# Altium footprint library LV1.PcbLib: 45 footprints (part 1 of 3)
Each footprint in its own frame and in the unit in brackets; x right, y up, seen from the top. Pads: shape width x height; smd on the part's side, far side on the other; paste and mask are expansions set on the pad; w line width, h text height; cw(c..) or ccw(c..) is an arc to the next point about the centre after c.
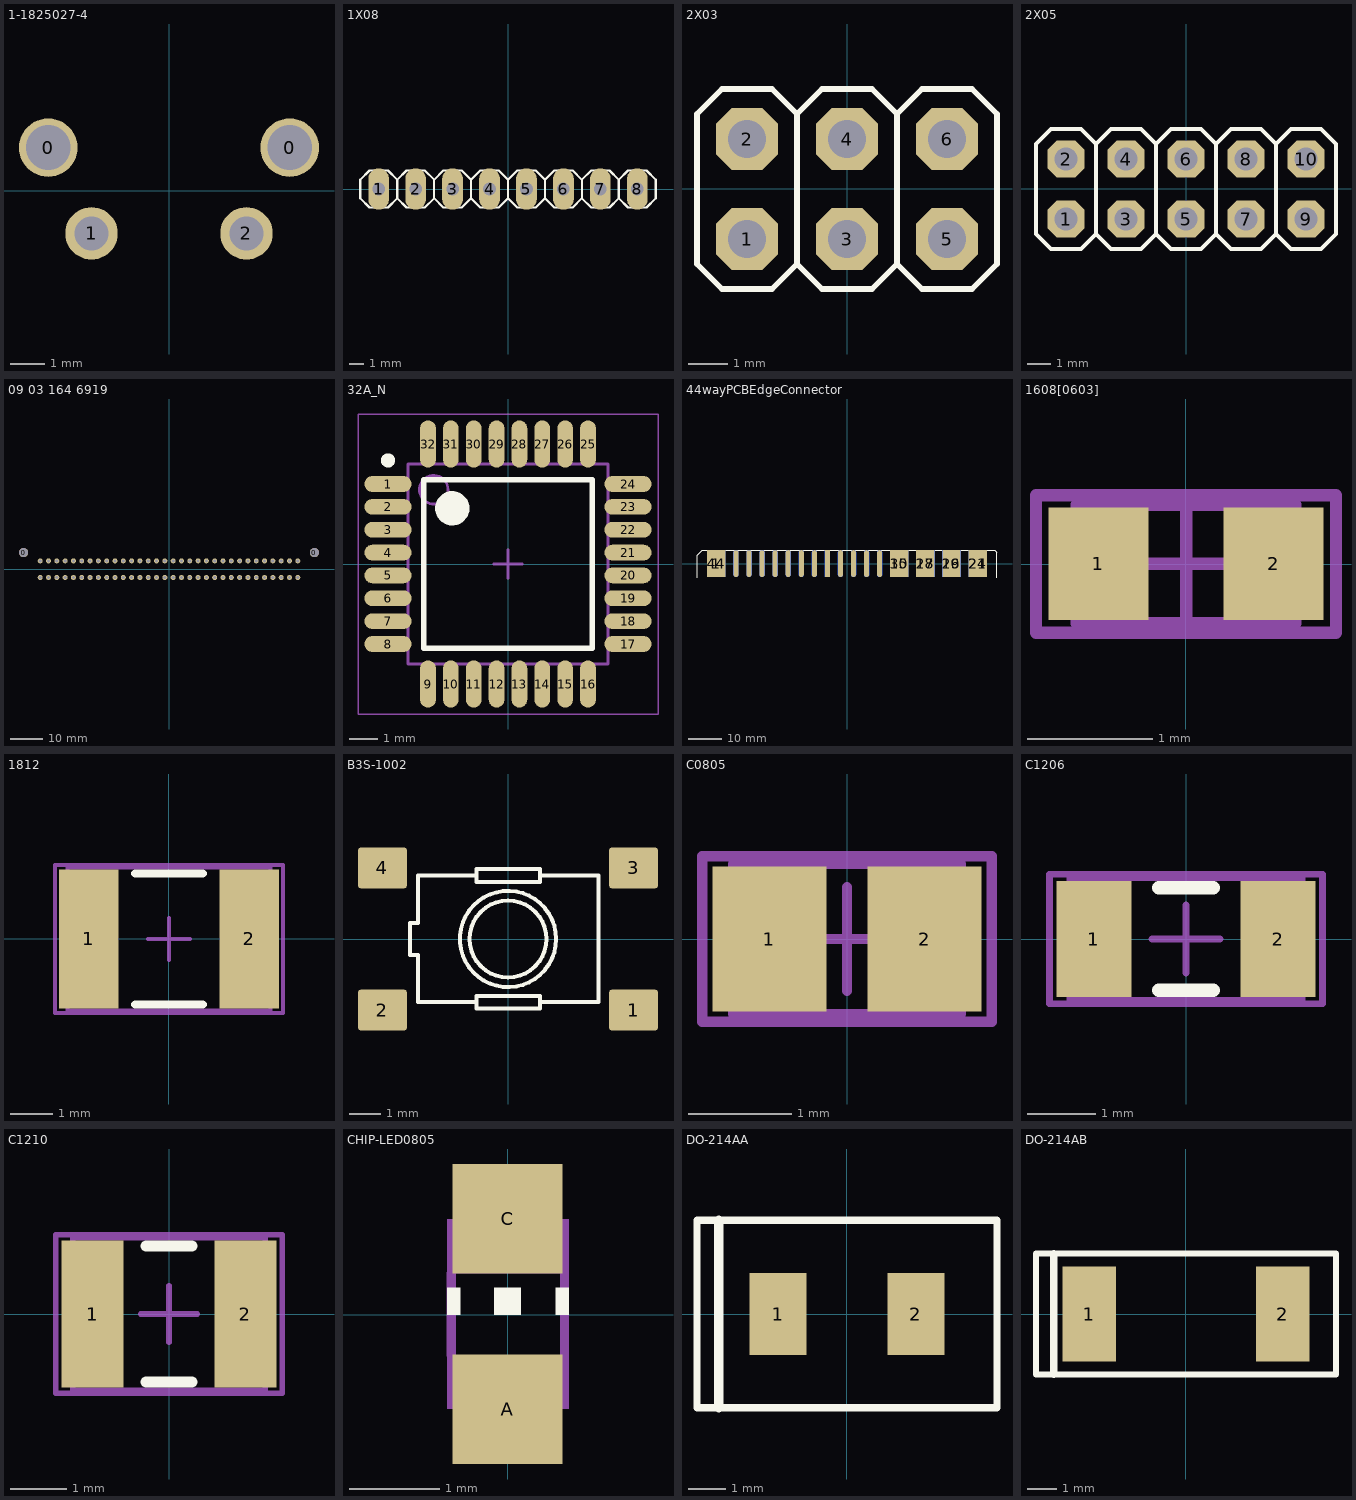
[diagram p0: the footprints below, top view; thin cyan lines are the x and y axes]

## 1-1825027-4 [mm]
pads (4):
  round 1.7 hole 1.3: 0(-3.505,1.245) 0(3.505,1.245)
  round 1.524 hole 0.99: 1(-2.25,-1.245) 2(2.25,-1.245)
3D body "c-1-1825027-4-g1-3d.stp": height 7, standoff -3.52, extent -4.204,-7.366 4.204,2.781

## 1X08 [mil]
height 338.58
pads (8):
  oval 56x112 hole 34: 1(-350,0) 2(-250,0) 3(-150,0) 4(-50,0) 5(50,0) 6(150,0) 7(250,0) 8(350,0)
Top Overlay:
  lines w6: -300,-25 -300,25 ; -300,-25 -325,-50 -375,-50 -400,-25 -400,25 -375,50 -325,50 -300,25 ; -300,-25 -275,-50 -225,-50 -200,-25 ; -300,25 -275,50 -225,50 -200,25 ; -200,-25 -175,-50 -125,-50 -100,-25 ; -200,-25 -200,25 ; -200,25 -175,50 -125,50 -100,25 ; -100,-25 -100,25 ; -100,-25 -75,-50 -25,-50 0,-25 ; -100,25 -75,50 -25,50 0,25 ; 0,-25 0,25 ; 0,-25 25,-50 75,-50 100,-25 ; 0,25 25,50 75,50 100,25 ; 100,-25 125,-50 175,-50 200,-25 ; 100,-25 100,25 ; 100,25 125,50 175,50 200,25 ; 200,-25 200,25 ; 200,-25 225,-50 275,-50 300,-25 ; 200,25 225,50 275,50 300,25 ; 300,-25 300,25 ; 300,-25 325,-50 375,-50 400,-25 400,25 375,50 325,50 300,25
Mechanical 16:
  rectangle: 240,-10 260,10
  rectangle: 140,-10 160,10
  rectangle: 40,-10 60,10
  rectangle: -60,-10 -40,10
  rectangle: -160,-10 -140,10
  rectangle: -260,-10 -240,10
  rectangle: -360,-10 -340,10
  rectangle: 340,-10 360,10

## 2X03 [mil]
height 338.58
pads (6):
  oct 62x62 hole 38: 1(-100,-50) 2(-100,50) 3(0,-50) 4(0,50) 5(100,-50) 6(100,50)
Top Overlay:
  lines w6: -50,-75 -75,-100 -125,-100 -150,-75 -150,75 -125,100 -75,100 -50,75 ; -50,-75 -25,-100 25,-100 50,-75 ; -50,-75 -50,75 ; -50,75 -25,100 25,100 50,75 ; 50,-75 50,75 ; 50,-75 75,-100 125,-100 150,-75 150,75 125,100 75,100 50,75
Mechanical 16:
  rectangle: -110,-60 -90,-40
  rectangle: -110,40 -90,60
  rectangle: -10,40 10,60
  rectangle: -10,-60 10,-40
  rectangle: 90,40 110,60
  rectangle: 90,-60 110,-40

## 2X05 [mil]
height 338.58
pads (10):
  oct 62x62 hole 38: 1(-200,-50) 2(-200,50) 3(-100,-50) 4(-100,50) 5(0,-50) 6(0,50) 7(100,-50) 8(100,50) 9(200,-50) 10(200,50)
Top Overlay:
  lines w6: -150,-75 -150,75 ; -150,-75 -125,-100 -75,-100 -50,-75 ; -150,-75 -175,-100 -225,-100 -250,-75 -250,75 -225,100 -175,100 -150,75 ; -150,75 -125,100 -75,100 -50,75 ; -50,-75 -25,-100 25,-100 50,-75 ; -50,-75 -50,75 ; -50,75 -25,100 25,100 50,75 ; 50,-75 50,75 ; 50,-75 75,-100 125,-100 150,-75 ; 50,-75 50,75 ; 50,75 75,100 125,100 150,75 ; 150,-75 175,-100 225,-100 250,-75 250,75 225,100 175,100 150,75 ; 150,-75 150,75 ; 150,-75 150,75
Mechanical 16:
  rectangle: 190,-60 210,-40
  rectangle: 190,40 210,60
  rectangle: 90,40 110,60
  rectangle: 90,-60 110,-40
  rectangle: -10,-60 10,-40
  rectangle: -10,40 10,60
  rectangle: -110,-60 -90,-40
  rectangle: -110,40 -90,60
  rectangle: -210,40 -190,60
  rectangle: -210,-60 -190,-40

## 09 03 164 6919 [mil]
pads (66):
  round 110.24 hole 110.24: 0(-1750,200) 0(1750,200)
  round 60 hole 39.37: 0(-1550,100) 1(-1450,100) 2(-1350,100) 3(-1250,100) 4(-1150,100) 5(-1050,100) 6(-950,100) 7(-850,100) 8(-750,100) 9(-650,100) 10(-550,100) 11(-450,100) 12(-350,100) 13(-250,100) 14(-150,100) 15(-50,100) 16(50,100) 17(150,100) 18(250,100) 19(350,100) 20(450,100) 21(550,100) 22(650,100) 23(750,100) 24(850,100) 25(950,100) 26(1050,100) 27(1150,100) 28(1250,100) 29(1350,100) 30(1450,100) 31(1550,100) 32(-1550,-100) 33(-1450,-100) 34(-1350,-100) 35(-1250,-100) 36(-1150,-100) 37(-1050,-100) 38(-950,-100) 39(-850,-100) 40(-750,-100) 41(-650,-100) 42(-550,-100) 43(-450,-100) 44(-350,-100) 45(-250,-100) 46(-150,-100) 47(-50,-100) 48(50,-100) 49(150,-100) 50(250,-100) 51(350,-100) 52(450,-100) 53(550,-100) 54(650,-100) 55(750,-100) 56(850,-100) 57(950,-100) 58(1050,-100) 59(1150,-100) 60(1250,-100) 61(1350,-100) 62(1450,-100) 63(1550,-100)
3D body "09031102020300_100072334MOD000B.STP": height 368.11, standoff -118.11, extent -1850,-100 1850.79,609.45

## 32A_N [mm] "Thin QFP, 32-Leads, Body 7x7mm, Pitch 0.8mm, IPC Medium Density"
height 1.2
pads (32):
  oval 1.65x0.55 smd: 1(-4.2,2.8) 2(-4.2,2) 3(-4.2,1.2) 4(-4.2,0.4) 5(-4.2,-0.4) 6(-4.2,-1.2) 7(-4.2,-2) 8(-4.2,-2.8) 17(4.2,-2.8) 18(4.2,-2) 19(4.2,-1.2) 20(4.2,-0.4) 21(4.2,0.4) 22(4.2,1.2) 23(4.2,2) 24(4.2,2.8)
  oval 0.55x1.65 smd: 9(-2.8,-4.2) 10(-2,-4.2) 11(-1.2,-4.2) 12(-0.4,-4.2) 13(0.4,-4.2) 14(1.2,-4.2) 15(2,-4.2) 16(2.8,-4.2) 25(2.8,4.2) 26(2,4.2) 27(1.2,4.2) 28(0.4,4.2) 29(-0.4,4.2) 30(-1.2,4.2) 31(-2,4.2) 32(-2.8,4.2)
Top Overlay:
  circle w0.25: c-4.2,3.625 r0.125
  circle w0.6: c-1.95,1.95 r0.3
  lines w0.2: -2.95,-2.95 -2.95,2.95 2.95,2.95 2.95,-2.95 -2.95,-2.95
Mechanical 13:
  circle w0.1: c-2.6,2.6 r0.5
  lines w0.1: -3.5,-3.5 -3.5,3.5 3.5,3.5 3.5,-3.5 -3.5,-3.5
Mechanical 15:
  lines w0.05: -5.25,-5.25 -5.25,5.25 5.25,5.25 5.25,-5.25 -5.25,-5.25
  lines w0.1: -0.5,0 0.5,0 ; 0,-0.5 0,0.5
3D body: height 1.2, standoff 0, extent -3.5,-3.5 3.5,3.5

## 44wayPCBEdgeConnector [mil]
pads (34):
  rect 218x320 smd: 1(-1560,0) 15(623,0) 17(936,0) 19(1247,0) 21(1560,0)
  oval 60x320 smd: 3(-1326,0) 4(-1170,0) 5(-1014,0) 6(-858,0) 7(-702,0) 8(-546,0) 9(-390,0) 11(-78,0) 12(78,0) 13(234,0) 14(390,0)
  rect 60x320 smd: 10(-234,0)
  rect 218x320 smd far side: 24(1560,0) 26(1247,0) 28(936,0) 30(623,0) 44(-1560,0)
  oval 60x320 smd far side: 31(390,0) 32(234,0) 33(78,0) 34(-78,0) 36(-390,0) 37(-546,0) 38(-702,0) 39(-858,0) 40(-1014,0) 41(-1170,0) 42(-1326,0)
  rect 60x320 smd far side: 35(-234,0)
Top Overlay:
  lines w10: -1791.34,-170 -1791.34,100 -1731.34,160 1765,160 1791.34,133.66 1791.34,100 1791.34,-170

## 1608[0603] [mm] "Chip Capacitor, Body 1.6x0.8mm, IPC High Density"
height 1.3
pads (2):
  rect 0.8x0.9 smd: 1(-0.7,0) 2(0.7,0)
Mechanical 13:
  lines w0.1: -0.875,-0.475 -0.875,0.475 0.875,0.475 0.875,-0.475 -0.875,-0.475
Mechanical 15:
  lines w0.1: -0.475,0 0.475,0 ; 0,-0.475 0,0.475 ; -1.2,-0.55 -1.2,0.55 1.2,0.55 1.2,-0.55 -1.2,-0.55
3D body: height 1.3, standoff 0, extent -0.875,-0.475 0.875,0.475

## 1812 [mm] "Chip Capacitor, Body 4.5x3.2mm, IPC High Density"
height 1.4
pads (2):
  rect 1.4x3.3 smd: 1(-1.9,0) 2(1.9,0)
Top Overlay:
  lines w0.2: -0.8,-1.55 0.8,-1.55 ; -0.8,1.55 0.8,1.55
Mechanical 13:
  lines w0.1: -2.4,-1.7 2.4,-1.7 2.4,1.7 -2.4,1.7 -2.4,-1.7
Mechanical 15:
  lines w0.1: -0.5,0 0.5,0 ; 0,-0.5 0,0.5 ; -2.7,-1.75 2.7,-1.75 2.7,1.75 -2.7,1.75 -2.7,-1.75
3D body: height 1.4, standoff 0, extent -2.4,-1.7 2.4,1.7

## B3S-1002 [mm]
height 7.12
pads (4):
  rrect15% 1.55x1.3 smd: 1(3.975,-2.25) 2(-3.975,-2.25) 3(3.975,2.25) 4(-3.975,2.25)
Top Overlay:
  circle w0.127: c0,0 r1.219
  circle w0.127: c0,0 r1.524
  lines w0.127: -1,-2 -2.85,-2 -2.85,-0.5 -3.1,-0.5 -3.1,0.508 -2.85,0.508 -2.85,2.007 -1,2.007 ; -1,-2 -1,-2.2 1.016,-2.2 1.016,-2 ; -1,-2 -1,-1.8 1.016,-1.8 1.016,-2 ; -1,2.007 -1,1.803 1.016,1.803 1.016,2.007 ; -1,2.007 -1,2.21 1.016,2.21 1.016,2.007 ; 1.016,-2 2.87,-2 2.87,2.007 1.016,2.007

## C0805 [mm] "Chip Capacitor, Body 2.0x1.3mm, IPC High Density"
height 1.4
pads (2):
  rect 1.1x1.4 smd: 1(-0.75,0) 2(0.75,0)
Mechanical 13:
  lines w0.1: -1.1,-0.725 1.1,-0.725 1.1,0.725 -1.1,0.725 -1.1,-0.725
Mechanical 15:
  lines w0.1: -0.5,0 0.5,0 ; 0,-0.5 0,0.5 ; -1.4,-0.8 1.4,-0.8 1.4,0.8 -1.4,0.8 -1.4,-0.8
3D body: height 1.4, standoff 0, extent -1.1,-0.725 1.1,0.725

## C1206 [mm] "Chip Capacitor, Body 3.2x1.6mm, IPC High Density"
height 1.3
pads (2):
  rect 1.1x1.7 smd: 1(-1.35,0) 2(1.35,0)
Top Overlay:
  lines w0.2: -0.4,-0.75 0.4,-0.75 ; -0.4,0.75 0.4,0.75
Mechanical 13:
  lines w0.1: -1.7,-0.9 1.7,-0.9 1.7,0.9 -1.7,0.9 -1.7,-0.9
Mechanical 15:
  lines w0.1: -0.5,0 0.5,0 ; 0,-0.5 0,0.5 ; -2,-0.95 2,-0.95 2,0.95 -2,0.95 -2,-0.95
3D body: height 1.3, standoff 0, extent -1.7,-0.9 1.7,0.9

## C1210 [mm] "Chip Capacitor, Body 3.2x2.5mm, IPC High Density"
height 1.3
pads (2):
  rect 1.1x2.6 smd: 1(-1.35,0) 2(1.35,0)
Top Overlay:
  lines w0.2: -0.4,-1.2 0.4,-1.2 ; -0.4,1.2 0.4,1.2
Mechanical 13:
  lines w0.1: -1.7,-1.35 -1.7,1.35 1.7,1.35 1.7,-1.35 -1.7,-1.35
Mechanical 15:
  lines w0.1: -0.5,0 0.5,0 ; 0,-0.5 0,0.5 ; -2,-1.4 -2,1.4 2,1.4 2,-1.4 -2,-1.4
3D body: height 1.3, standoff 0, extent -1.7,-1.35 1.7,1.35

## CHIP-LED0805 [mil]
height 280.31
pads (2):
  rect 48x48 smd: A(0,-41.34) C(0,42)
Top Overlay:
  rectangle: -26.57,0 -20.67,12
  rectangle: 21,0 27,12
  rectangle: -5.91,0 6,12
Mechanical 16:
  rectangle: -26.57,18 27,42
  rectangle: -26.57,-41.34 27,-17.72
  lines w4: -24.61,-17.72 -24.61,18 ; 25,-18.7 25,18

## DO-214AA [mm]
height 7.12
pads (2):
  rect 1.52x2.18 smd: 1(-1.84,0) 2(1.84,0)
Top Overlay:
  lines w0.2: -4.01,-2.5 -4.01,0 -4.01,2.5 4.01,2.5 4.01,-2.5 -4.01,-2.5
  lines w0.254: -3.429,-2.5 -3.429,2.5

## DO-214AB [mm]
height 7.12
pads (2):
  rect 1.8x3.2 smd: 1(-3.25,0) 2(3.25,0)
Top Overlay:
  lines w0.2: -5.05,-2.032 5.05,-2.032 5.05,2.032 -5.05,2.032 -5.05,0 -5.05,-2.032
  lines w0.254: -4.445,-2.032 -4.445,2.032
